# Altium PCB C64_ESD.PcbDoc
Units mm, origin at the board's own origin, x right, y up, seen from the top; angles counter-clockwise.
Board outline 62 x 12 mm, 2 copper layers (Top Layer, Bottom Layer), stack 1.53 mm thick; 6 components, 0 nets, 46 pads, 0 vias.
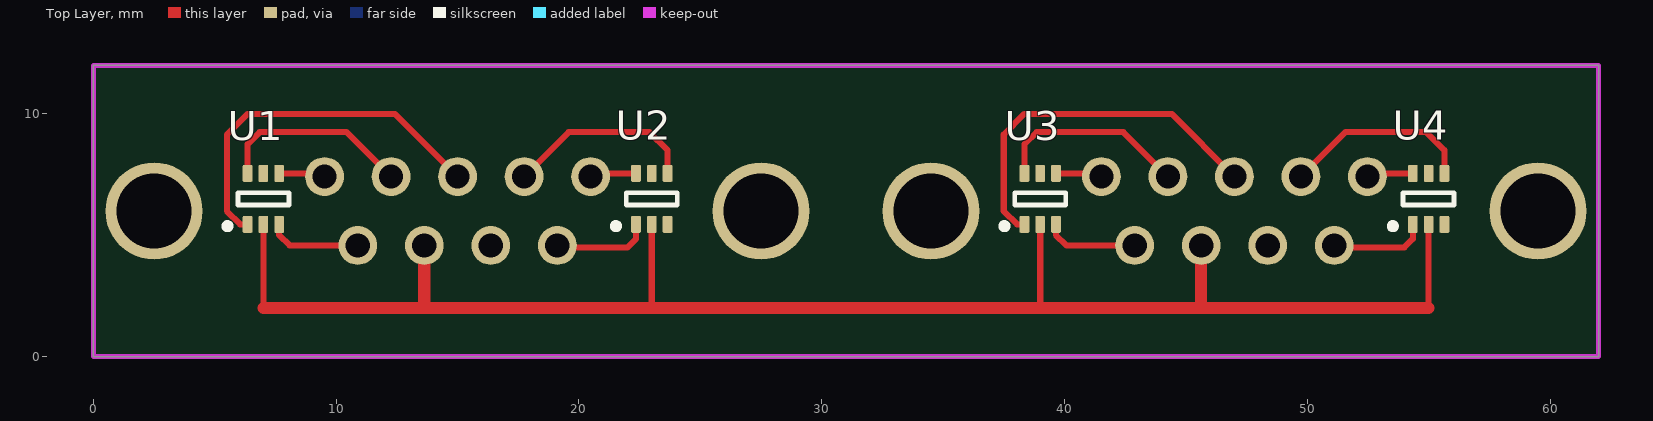
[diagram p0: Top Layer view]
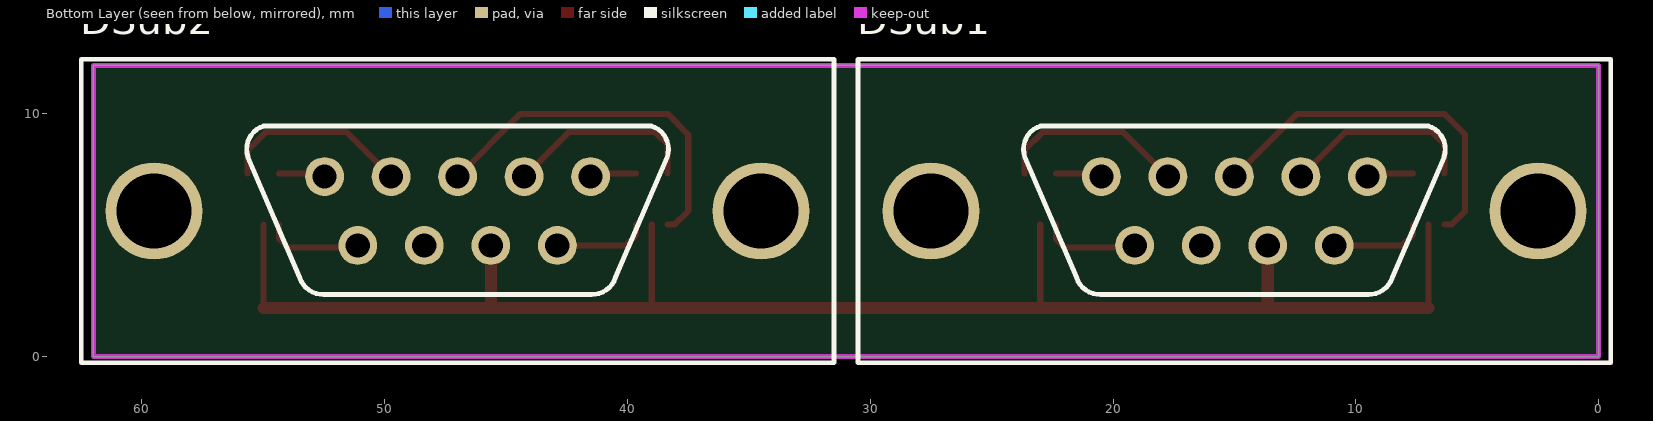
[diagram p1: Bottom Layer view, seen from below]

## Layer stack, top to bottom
Top Solder: solder mask 0.01, Solder Resist, Dk 3.5
Top Layer: signal copper 0.035
Dielectric1: core 1.46, FR-4, Dk 4.8
Bottom Layer: signal copper 0.035
Bottom Solder: solder mask 0.01, Solder Resist, Dk 3.5

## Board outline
0,0 0,12 62,12 62,0

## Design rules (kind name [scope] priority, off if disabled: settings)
Clearance Clearance_Fiducial [All vs HasFootprint('MISC_Fiducial_1mm')] p1: gap=0.5 ignorepadtopadclearanceinfootprint=FALSE except(0: Arc-Hole Track-Hole SMDPad-Hole THPad-Hole Via-Hole Fill-Hole Poly-Hole Region-Hole Text-Hole)
Clearance "Clearance_Polygon to Text" [IsText AND OnSignal vs InPolygon] p2: gap=-0.1 ignorepadtopadclearanceinfootprint=FALSE except(0: Arc-Hole Track-Hole SMDPad-Hole THPad-Hole Via-Hole Fill-Hole Poly-Hole Region-Hole Text-Hole)
Clearance Clearance_GND_Keepout [InNet('GND') vs OnLayer('Keep-Out Layer')] p3: gap=0.5 ignorepadtopadclearanceinfootprint=FALSE except(0: Arc-Hole Track-Hole SMDPad-Hole THPad-Hole Via-Hole Fill-Hole Poly-Hole Region-Hole Text-Hole) // GND nach Keepout
Clearance Clearance_GND_PolygonPlane [(InPolygon AND InNet('GND'))] p4: gap=0.3 ignorepadtopadclearanceinfootprint=FALSE except(0: Arc-Hole Track-Hole SMDPad-Hole THPad-Hole Via-Hole Fill-Hole Poly-Hole Region-Hole Text-Hole)
Clearance "Clearance ADUC841 Pads" [HasFootprint('TQFP65P1400X1400-52N')] p5: gap=0.25 ignorepadtopadclearanceinfootprint=FALSE except(0: Arc-Hole Track-Hole SMDPad-Hole THPad-Hole Via-Hole Fill-Hole Poly-Hole Region-Hole Text-Hole) // ADUC_Pads
Clearance "Clearance ADUC7026 Pads" [HasFootprint('TQFP50P1400X1400-80N')] p6: gap=0.2 ignorepadtopadclearanceinfootprint=FALSE except(0: Arc-Hole Track-Hole SMDPad-Hole THPad-Hole Via-Hole Fill-Hole Poly-Hole Region-Hole Text-Hole) // ADUC_Pads
Clearance [All] p7: gap=0.25 ignorepadtopadclearanceinfootprint=FALSE except(0: Arc-Hole Track-Hole SMDPad-Hole THPad-Hole Via-Hole Fill-Hole Poly-Hole Region-Hole Text-Hole)
ComponentClearance [All] p1: gap=0.25 collisioncheckmode=3 verticalgap=0.25 showdistances=FALSE
DiffPairsRouting [All] p1: maxlimit=0.25 minlimit=0.25 mostfreqgap=0.25 toplayer_minwidth=0.381 toplayer_maxwidth=0.381 toplayer_prefwidth=0.381 bottomlayer_minwidth=0.381 bottomlayer_maxwidth=0.381 bottomlayer_prefwidth=0.381 maxuncoupledlength=10
FabricationTestPointUsage TestPointUsage [All] p1: valid=0 allowmultiple=FALSE
FabricationTestpoint Testpoint [All] p1: side=3 testpointundercomponent=TRUE minsize=1.016 maxsize=2.54 preferedsize=1.524 minholesize=0 maxholesize=1.016 preferedholesize=0.813 testpointgrid=0.025 allowsidetop=TRUE allowsidebottom=TRUE usegrid=TRUE gridtolerance=0
Height [All] p1: minheight=0 maxheight=60 prefheight=12
HoleSize [All] p1: absolutevalues=TRUE maxlimit=20 minlimit=0.3 maxpercent=80.000 minpercent=20.000
HoleToHoleClearance [All] p1: gap=0.3 allowstackedmicrovias=TRUE
MinimumAnnularRing [All] p1: minimumring=0.2
MinimumSolderMaskSliver [All] p1: minsoldermaskwidth=0.1
NetAntennae [All] p1: netantennaetolerance=0.5
PlaneClearance [All] p1: clearance=0.25
PlaneConnect [All] p1: planeconnectstyle=Relief reliefexpansion=0.5 reliefentries=4 reliefconductorwidth=0.25 reliefairgap=0.25
PolygonConnect PolygonConnect_VIA [isvia] p1: connectstyle=Direct reliefconductorwidth=0.254 reliefentries=4 polygonreliefangle="90 Angle" airgapwidth=0.254
PolygonConnect [All] p2: connectstyle=Relief reliefconductorwidth=0.3 reliefentries=4 polygonreliefangle="90 Angle" airgapwidth=0.25
RoutingCorners [All] p1: cornerstyle=45-Degree minsetback=2 maxsetback=10
RoutingVias [All] p1: holewidth=0.4 width=0.8 viastyle="Through Hole" minholewidth=0.3 minwidth=0.7 maxholewidth=3 maxwidth=6
ShortCircuit ShortCircuit_Via_in_Thermalpad [isvia and not InAnyNet vs ispad and not InAnyNet] p1: allowed=TRUE // VIA in Thermal Pad with no Net is OK
ShortCircuit "ShortCircuit_Polygon to Text" [IsText vs InPolygon] p2: allowed=TRUE
ShortCircuit [All] p3: allowed=FALSE
SilkToSilkClearance [All] p1: silktosilkclearance=0
SilkToSolderMaskClearance SilkscreenOverComponentPads [IsPad] p1: minsilkscreentomaskgap=0.15 clearancetoexposedcopper=TRUE
SolderMaskExpansion [All] p1: expansion=0.05
Width Width_Trackends [All] p1 off: maxlimit=10 minlimit=0.25 preferedwidth=0.3 checkconnectedcopper=TRUE
Width [All] p2: maxlimit=10 minlimit=0.25 preferedwidth=0.3
15 further rules are at their usual default settings.

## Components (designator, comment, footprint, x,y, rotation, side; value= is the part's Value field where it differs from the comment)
DSub1 "Comment" CON_DSUB9f_straight 15,6 r180 bottom
DSub2 "Comment" CON_DSUB9f_straight 47,6 r180 bottom
U1 "Comment" SOT65P240X110-6N 7,6.5 r90 top
U2 "Comment" SOT65P240X110-6N 23,6.5 r90 top
U3 "Comment" SOT65P240X110-6N 39,6.5 r90 top
U4 "Comment" SOT65P240X110-6N 55,6.5 r90 top

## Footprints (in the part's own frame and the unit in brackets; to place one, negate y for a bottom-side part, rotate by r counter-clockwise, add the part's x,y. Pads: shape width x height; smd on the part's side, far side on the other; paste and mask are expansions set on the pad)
CON_DSUB9f_straight [mm] "Harting DSub9 9pin female straight"
  round 1.6 hole 1: 1(5.48,1.42) 2(2.74,1.42) 3(0,1.42) 4(-2.74,1.42) 5(-5.48,1.42) 6(4.11,-1.42) 7(1.37,-1.42) 8(-1.37,-1.42) 9(-4.11,-1.42)
  round 4 hole 3.1: 10(-12.5,0) 11(12.5,0)
  silkscreen extent -15.5,-6.25 15.5,6.25, body extent -15.5,-6.25 15.5,6.25, height 12.4
SOT65P240X110-6N [mm] "SOT23, 6-Leads, Body 2,10x2,40mm, Pitch 0,65mm, IPC Medium Density"
  rrect25% 0.7x0.4 smd: 1(-1.05,0.65) 2(-1.05,0) 3(-1.05,-0.65) 4(1.05,-0.65) 5(1.05,0) 6(1.05,0.65)
  silkscreen extent -1.25,-1.05 0.25,1.6, body extent -1.2,-1.05 1.2,1.05, height 1.1

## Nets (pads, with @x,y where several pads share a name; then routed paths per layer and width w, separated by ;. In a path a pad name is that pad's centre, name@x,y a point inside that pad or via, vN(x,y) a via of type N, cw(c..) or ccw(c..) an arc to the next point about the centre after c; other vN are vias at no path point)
pads on no net: DSub1.1 DSub1.2 DSub1.3 DSub1.4 DSub1.5 DSub1.6 DSub1.7 DSub1.8 DSub1.9 DSub1.10 DSub1.11 DSub2.1 DSub2.2 DSub2.3 DSub2.4 DSub2.5 DSub2.6 DSub2.7 DSub2.8 DSub2.9 DSub2.10 DSub2.11 U1.1 U1.2 U1.3 U1.4 U1.5 U1.6 U2.1 U2.2 U2.3 U2.4 U2.5 U2.6 U3.1 U3.2 U3.3 U3.4 U3.5 U3.6 U4.1 U4.2 U4.3 U4.4 U4.5 U4.6
copper on no net: | length 152.6
  Top Layer w0.254: 6.35,5.45 6.05,5.45 5.5,6 5.5,9.15 6.35,10 11.75,10 12.42,10 15,7.42 ; 6.35,7.55 6.35,8.75 6.85,9.25 9,9.25 10.43,9.25 12.26,7.42 ; 7,2 7,5.45 ; 7.65,5.45 7.65,5.01 8.08,4.58 10.89,4.58 ; 7.65,7.55 9.39,7.55 9.52,7.42 ; 17.74,7.42 19.57,9.25 22.9,9.25 23.65,8.5 23.65,7.55 ; 19.11,4.58 19.19,4.5 22,4.5 22.35,4.85 22.35,5.45 ; 20.48,7.42 20.61,7.55 22.35,7.55 ; 23,2.032 23,5.45 ; 38.35,5.45 38.05,5.45 37.5,6 37.5,9.15 38.35,10 43.75,10 44.42,10 47,7.42 ; 38.35,7.55 38.35,8.75 38.85,9.25 41,9.25 42.43,9.25 44.26,7.42 ; 39,2.032 39,5.45 ; 39.65,5.45 39.65,5.01 40.08,4.58 42.89,4.58 ; 39.65,7.55 41.39,7.55 41.52,7.42 ; 49.74,7.42 51.57,9.25 54.9,9.25 55.65,8.5 55.65,7.55 ; 51.11,4.58 51.19,4.5 54,4.5 54.35,4.85 54.35,5.45 ; 52.48,7.42 52.61,7.55 54.35,7.55 ; 55,2 55,5.45
  Top Layer w0.5: 7,2 55,2 ; 13.63,2 13.63,4.58 ; 45.63,2 45.63,4.58

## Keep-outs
Keep-Out Layer:
  the board outline again, w0.2

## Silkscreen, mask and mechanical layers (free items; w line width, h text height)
M01_PhyOutL:
  the board outline again, w0.2
M02_MillOutL(2mm):
  lines w2: -1,-1 -1,13 63,13 63,-1 -1,-1

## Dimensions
15,7.42 to 47,7.42 on M03_Dim
0,12 to 62,12 on M03_Dim
0,12 to 0,0 on M03_Dim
